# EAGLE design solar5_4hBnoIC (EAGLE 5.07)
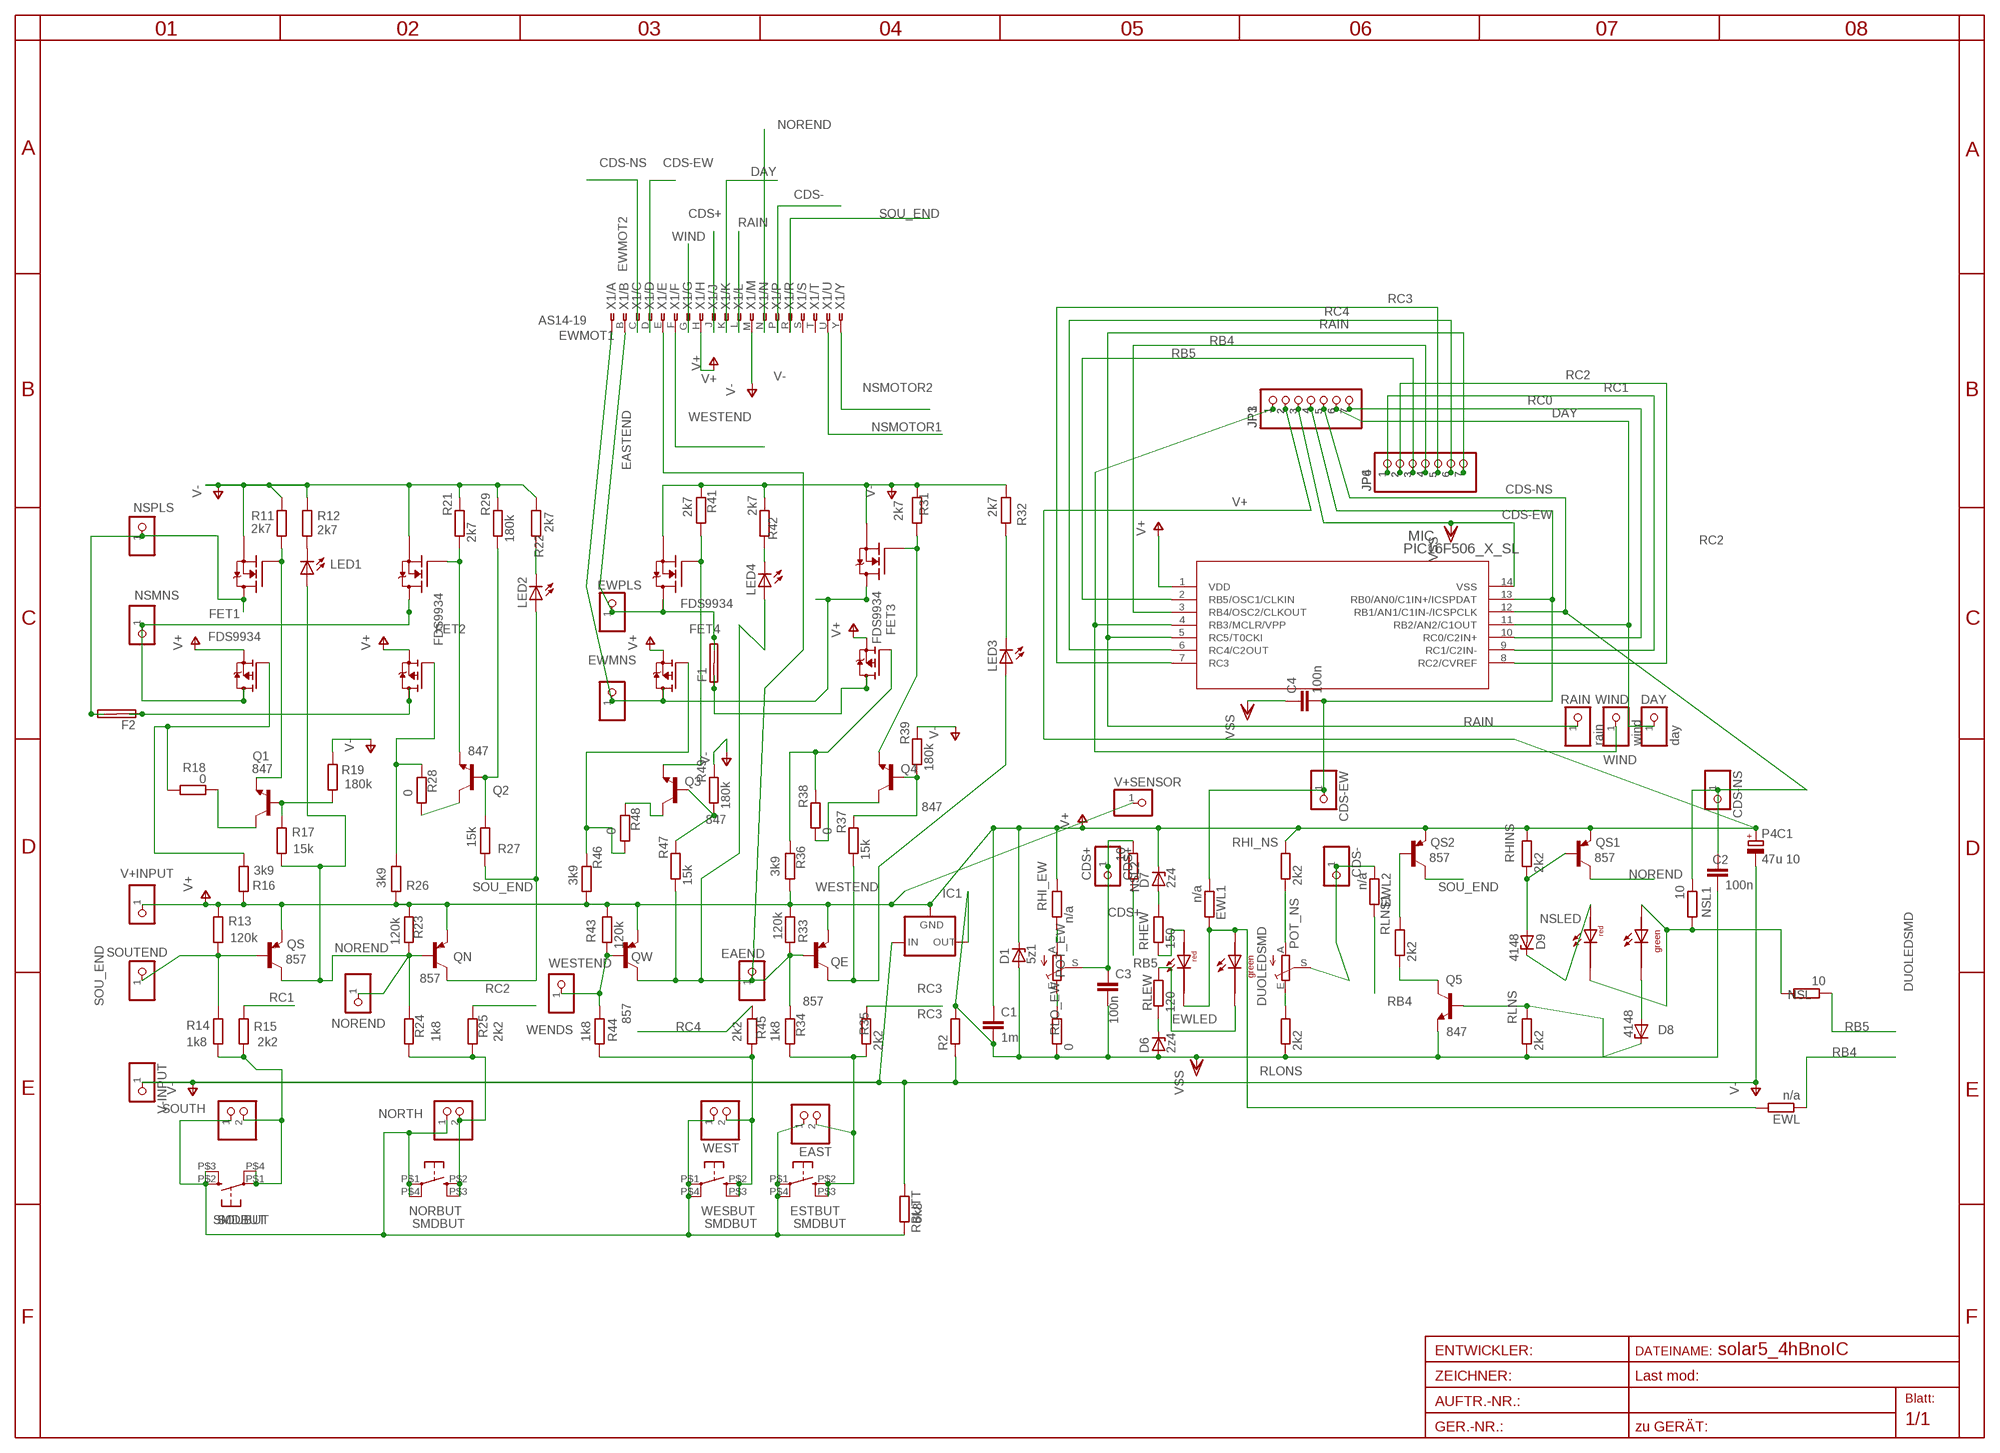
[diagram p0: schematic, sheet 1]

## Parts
C1  1m  C-EUC1206  [C1206]
C2  100n  C-EUC1206  [C1206]
C3  100n  C-EUC1206  [C1206]
C4  100n  C-EUC1206  [C1206]
CDS+  CDS+  PINHD-1X1INCH  [1X01]
CDS-  PINHD-1X1INCH  [1X01]
CDS-EW  PINHD-1X1INCH  [1X01]
CDS-NS  PINHD-1X1INCH  [1X01]
D1  5z1  ZENER-DIODESOD80C  [SOD80C]
D6  2z4  ZENER-DIODESOD80C  [SOD80C]
D7  2z4  ZENER-DIODESOD80C  [SOD80C]
D8  4148  ZENER-DIODESOD80C  [SOD80C]
D9  4148  ZENER-DIODESOD80C  [SOD80C]
DAY  day  PINHD-1X1INCH  [1X01]
EAEND  PINHD-1X1INCH  [1X01]
EAST  PINHD-1X2STR  [1X02]
ESTBUT  SMDBUT  [SMD10/5]
EWL  n/a  R-EU_R0603  [R0603]
EWL1  n/a  R-EU_R0805  [R0805]
EWL2  n/a  R-EU_R0402  [R0402]
EWLED  DUOLEDSMD  [DUOLEDSMD]
EWMNS  PINHD-1X1INCH  [1X01]
EWPLS  PINHD-1X1INCH  [1X01]
F1  SHK20L7MM5  [7MM5]
F2  SHK20L7MM5  [7MM5]
FET1  FDS9934  [SO-8]
FET2  FDS9934  [SO-8]
FET3  FDS9934  [SO-8]
FET4  FDS9934  [SO-8]
IC1  79LXX  [79LXX]
JP1  PINHD-1X7  [1X07]
JP3  PINHD-1X7  [1X07]
JP4  PINHD-1X7  [1X07]
JP6  PINHD-1X7  [1X07]
LED1  LEDCHIPLED_1206  [CHIPLED_1206]
LED2  LEDCHIPLED_1206  [CHIPLED_1206]
LED3  LEDCHIPLED_1206  [CHIPLED_1206]
LED4  LEDCHIPLED_1206  [CHIPLED_1206]
MIC  PIC16F506_X_SL  [SOIC14_N_MC]
NORBUT  SMDBUT  [SMD10/5]
NOREND  PINHD-1X1INCH  [1X01]
NORTH  PINHD-1X2STR  [1X02]
NSL  10  R-EU_R0603  [R0603]
NSL1  10  R-EU_R0805  [R0805]
NSL2  10  R-EU_R0603  [R0603]
NSLED  DUOLEDSMD  [DUOLEDSMD]
NSMNS  PINHD-1X1INCH  [1X01]
NSPLS  PINHD-1X1INCH  [1X01]
P4C1  47u 10  CPOL-EUE5-8.5  [E5-8,5]
POT_EW  TRIM_EU-CA6V  [CA6V]
POT_NS  TRIM_EU-CA6V  [CA6V]
Q1  847  BC847ASMD  [SOT23]
Q2  847  BC847ASMD  [SOT23]
Q3  847  BC847ASMD  [SOT23]
Q4  847  BC847ASMD  [SOT23]
Q5  847  BC847ASMD  [SOT23]
QE  857  BC327SMD  [SOT23-BEC]
QN  857  BC327SMD  [SOT23-BEC]
QS  857  BC327SMD  [SOT23-BEC]
QS1  857  BC327SMD  [SOT23-BEC]
QS2  857  BC327SMD  [SOT23-BEC]
QW  857  BC327SMD  [SOT23-BEC]
R2  R-EU_R0805  [R0805]
R11  2k7  R-EU_R1206  [R1206]
R12  2k7  R-EU_R0805  [R0805]
R13  120k  R-EU_R0805  [R0805]
R14  1k8  R-EU_R1206  [R1206]
R15  2k2  R-EU_R0805  [R0805]
R16  3k9  R-EU_R0805  [R0805]
R17  15k  R-EU_R0805  [R0805]
R18  0  R-EU_R0805  [R0805]
R19  180k  R-EU_R1206  [R1206]
R21  2k7  R-EU_R0805  [R0805]
R22  2k7  R-EU_R0805  [R0805]
R23  120k  R-EU_R0805  [R0805]
R24  1k8  R-EU_R0805  [R0805]
R25  2k2  R-EU_R0805  [R0805]
R26  3k9  R-EU_R1206  [R1206]
R27  15k  R-EU_R0805  [R0805]
R28  0  R-EU_R0805  [R0805]
R29  180k  R-EU_R0805  [R0805]
R31  2k7  R-EU_R0805  [R0805]
R32  2k7  R-EU_R0805  [R0805]
R33  120k  R-EU_R0805  [R0805]
R34  1k8  R-EU_R0805  [R0805]
R35  2k2  R-EU_R0805  [R0805]
R36  3k9  R-EU_R0805  [R0805]
R37  15k  R-EU_R0805  [R0805]
R38  0  R-EU_R0805  [R0805]
R39  180k  R-EU_R1206  [R1206]
R41  2k7  R-EU_R0805  [R0805]
R42  2k7  R-EU_R0805  [R0805]
R43  120k  R-EU_R0805  [R0805]
R44  1k8  R-EU_R0805  [R0805]
R45  2k2  R-EU_R0805  [R0805]
R46  3k9  R-EU_R0805  [R0805]
R47  15k  R-EU_R0805  [R0805]
R48  0  R-EU_R0805  [R0805]
R49  180k  R-EU_R0805  [R0805]
RAIN  rain  PINHD-1X1INCH  [1X01]
RBUTT  6k8  R-EU_R0805  [R0805]
RHEW  150  R-EU_R0805  [R0805]
RHI_EW  n/a  R-EU_R0805  [R0805]
RHI_NS  2k2  R-EU_R1206  [R1206]
RHINS  2k2  R-EU_R0805  [R0805]
RLEW  120  R-EU_R0805  [R0805]
RLNS  2k2  R-EU_R0805  [R0805]
RLNS1  2k2  R-EU_R0805  [R0805]
RLO_EW  0  R-EU_R1206  [R1206]
RLONS  2k2  R-EU_R0805  [R0805]
SOUBUT  SMDBUT  [SMD10/5]
SOUTEND  PINHD-1X1INCH  [1X01]
SOUTH  PINHD-1X2STR  [1X02]
V+INPUT  PINHD-1X1INCH  [1X01]
V+SENSOR  PINHD-1X10MM6  [1X01M]
V-INPUT  PINHD-1X10MM6  [1X01M]
WENDS  PINHD-1X1INCH  [1X01]
WESBUT  SMDBUT  [SMD10/5]
WEST  PINHD-1X2STR  [1X02]
WIND  wind  PINHD-1X1INCH  [1X01]
X1  AS14-19  AS14-19OLIVE  [Y28M-19TK]

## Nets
A1: POT_EW.A RHI_EW.1
A2: POT_NS.A RHI_NS.1
CDS+: C3.1 CDS+.1 NSL2.1 POT_EW.S X1.J
CDS-: CDS-.1 EWL2.1 POT_NS.S X1.P
CDS-EW: C4.2 CDS-EW.1 EWL1.1 JP1.4 JP3.4 MIC.13(RB0/AN0/C1IN+/ICSPDAT) X1.D
CDS-NS: C2.1 CDS-NS.1 JP1.5 JP3.5 MIC.12(RB1/AN1/C1IN-/ICSPCLK) NSL1.1 X1.C
DAY: DAY.1 JP1.6 JP3.6 MIC.11(RB2/AN2/C1OUT) X1.K
DRP2: F2.1A F2.1B FET2.5(Q2D2) FET2.6(Q2D)
DRP3: F1.1A F1.1B FET3.5(Q2D2) FET3.6(Q2D)
E2: POT_NS.E RLONS.2
EASTEND: EAEND.1 LED4.A QE.B QW.C R33.2 R34.2 R47.1 X1.E
EWMOT1: EWMNS.1 FET3.7(Q1D2) FET3.8(Q1D1) FET4.5(Q2D2) FET4.6(Q2D) X1.A
EWMOT2: EWPLS.1 F1.2A F1.2B FET4.7(Q1D2) FET4.8(Q1D1) X1.B
F1NG: FET1.2(Q1G) Q1.2(E) R11.1
F1PG: FET1.4(Q2G) R16.2 R18.1
F2NG: FET2.2(Q1G) Q2.2(E) R21.1
F2PG: FET2.4(Q2G) R26.2 R28.2
N$1: D9.A QS1.B RHINS.1
N$2: D8.A NSLED.CGRN
N$3: D8.C Q5.1(B) RLNS.2
N$4: QS2.B RLNS1.2
N$5: LED1.C R12.1
N$6: Q3.1(B) R47.2 R49.1
N$7: FET4.4(Q2G) R46.2 R48.1
N$8: LED2.C R22.1
N$9: R14.1 R15.1 SOUBUT.P$1(P) SOUBUT.P$4(P1) SOUTH.2
N$10: D9.C NSLED.ARED
N$11: EAST.2 ESTBUT.P$2(S) ESTBUT.P$3(S1) R34.1 R35.1
N$12: Q2.3(C) R28.1
N$13: FET3.2(Q1G) Q4.2(E) R31.1
N$14: D7.A RHEW.2
N$15: LED4.C R42.1
N$16: Q5.3(C) RLNS1.1
N$17: NORBUT.P$2(S) NORBUT.P$3(S1) NORTH.2 R24.1 R25.1
N$19: Q1.1(B) R17.2 R19.1
N$20: Q1.3(C) R18.2
N$21: POT_EW.E RLO_EW.2
N$23: Q2.1(B) R27.2 R29.1
N$25: EWLED.ARED RHEW.1
N$26: FET3.4(Q2G) R36.2 R38.2
N$27: D6.C RLEW.1
N$28: EWLED.CGRN RLEW.2
N$29: EAST.1 ESTBUT.P$1(P) ESTBUT.P$4(P1) NORBUT.P$1(P) NORBUT.P$4(P1) NORTH.1 RBUTT.2 SOUBUT.P$2(S) SOUBUT.P$3(S1) SOUTH.1 WESBUT.P$1(P) WESBUT.P$4(P1) WEST.1
N$30: Q4.1(B) R37.2 R39.1
N$31: Q3.3(C) R48.2
N$32: FET4.2(Q1G) Q3.2(E) R41.1
N$33: Q4.3(C) R38.1
N$39: R44.1 R45.1 WESBUT.P$2(S) WESBUT.P$3(S1) WEST.2
N$56: LED3.C R32.1
NOREND: LED1.A NOREND.1 QN.B QS1.C QS.C R17.1 R23.1 R24.2 X1.N
NSMOTOR1: F2.2A F2.2B FET1.7(Q1D2) FET1.8(Q1D1) NSPLS.1 X1.U
NSMOTOR2: FET1.5(Q2D2) FET1.6(Q2D) FET2.7(Q1D2) FET2.8(Q1D1) NSMNS.1 X1.Y
RAIN: JP4.7 JP6.7 MIC.5(RC5/T0CKI) RAIN.1 X1.L
RB4: EWL2.2 EWL.1 JP4.4 JP6.4 MIC.3(RB4/OSC2/CLKOUT)
RB4B: EWL1.2 EWL.2 EWLED.AGRN EWLED.CRED
RB5: JP4.3 JP6.3 MIC.2(RB5/OSC1/CLKIN) NSL2.2 NSL.1
RB5B: NSL1.2 NSL.2 NSLED.AGRN NSLED.CRED
RC0: JP1.7 JP3.7 MIC.10(RC0/C2IN+)
RC1: JP4.1 JP6.1 MIC.9(RC1/C2IN-) R15.2
RC2: JP4.2 JP6.2 MIC.8(RC2/CVREF) R25.2
RC3: JP4.5 JP6.5 MIC.7(RC3) R35.2
RC4: JP4.6 JP6.6 MIC.6(RC4/C2OUT) R45.2
SOU_END: LED2.A QN.C QS2.C QS.B R13.1 R14.2 R27.1 SOUTEND.1 X1.R
V+: C1.1 D1.C D7.C FET1.3(Q2S) FET2.3(Q2S) FET3.3(Q2S) FET4.3(Q2S) IC1.GND JP1.2 JP3.2 MIC.1(VDD) P4C1.+ QE.E QN.E QS1.E QS2.E QS.E QW.E R13.2 R16.1 R23.2 R26.1 R33.1 R36.1 R43.2 R46.1 RHI_EW.2 RHI_NS.2 RHINS.2 V+INPUT.1 V+SENSOR.1 X1.H
V-: FET1.1(Q1S) FET2.1(Q1S) FET3.1(Q1S) FET4.1(Q1S) IC1.IN P4C1.- R2.1 R11.2 R12.2 R19.2 R21.2 R22.2 R29.2 R31.2 R32.2 R39.2 R41.2 R42.2 R49.2 RBUTT.1 V-INPUT.1 X1.M
VSS: C1.2 C2.2 C3.2 C4.1 D1.A D6.A IC1.OUT JP1.3 JP3.3 MIC.14(VSS) Q5.2(E) R2.2 RLNS.1 RLO_EW.1 RLONS.1
WESTEND: LED3.A QE.C QW.B R37.1 R43.1 R44.2 WENDS.1 X1.F
WIND: JP1.1 JP3.1 MIC.4(RB3/MCLR/VPP) WIND.1 X1.G
Unconnected: X1.S X1.T

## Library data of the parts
C1-C4 = rcl-2:C-EU: CAPACITOR, European symbol
CDS+ CDS- CDS-EW CDS-NS DAY EAEND EWMNS EWPLS NOREND NSMNS NSPLS RAIN SOUTEND V+INPUT V+SENSOR V-INPUT WENDS WIND = pinhead(2):PINHD-1X1: PIN HEADER
D1 D6-D9 = diode-1:ZENER-DIODE: Z-Diode
EAST NORTH SOUTH WEST = pinhead:PINHD-1X2: PIN HEADER
ESTBUT NORBUT SOUBUT WESBUT = switch-omron:SMDBUT
EWL EWL1 EWL2 NSL NSL1 NSL2 R2 R11-R19 R21-R29 R31-R39 R41-R49 RBUTT RHEW RHI_EW RHI_NS RHINS RLEW RLNS RLNS1 RLO_EW RLONS = rcl-2:R-EU_: RESISTOR, European symbol
EWLED NSLED = led:DUOLEDSMD
F1 F2 = fuse:SHK20L: FUSE HOLDER 5 x 20 mm, SH contact, SHH1 Schukat, E1073 Buerklin
FET1-FET4 = transistor-fet:FDS9934
IC1 = v-reg:79LXX: VOLTAGE REGULATOR
JP1 JP3 JP4 JP6 = pinhead:PINHD-1X7: PIN HEADER
LED1-LED4 = led:LED: LED
MIC = pic16f506mc:PIC16F506_X_SL
P4C1 = rcl:CPOL-EU: POLARIZED CAPACITOR, European symbol
POT_EW POT_NS = pot:TRIM_EU-: POTENTIOMETER
Q1-Q5 = transistor-npn:BC847*: NPN Transistor
QE QN QS QS1 QS2 QW = transistor-pnp:BC327*: PNP Transistror
X1 = con-deutsch:AS14-19: DEUTSCH Connector

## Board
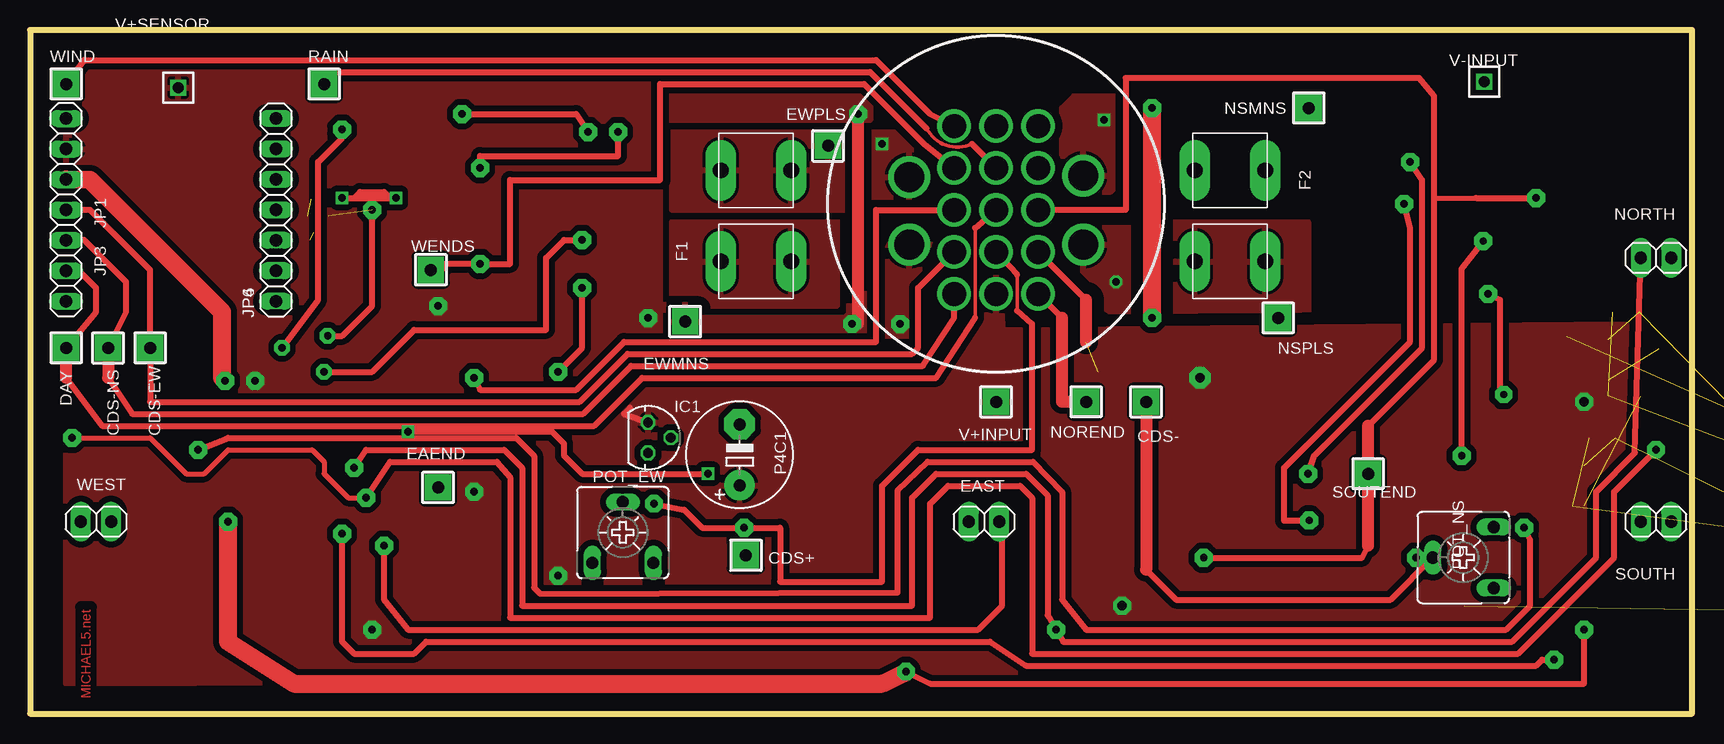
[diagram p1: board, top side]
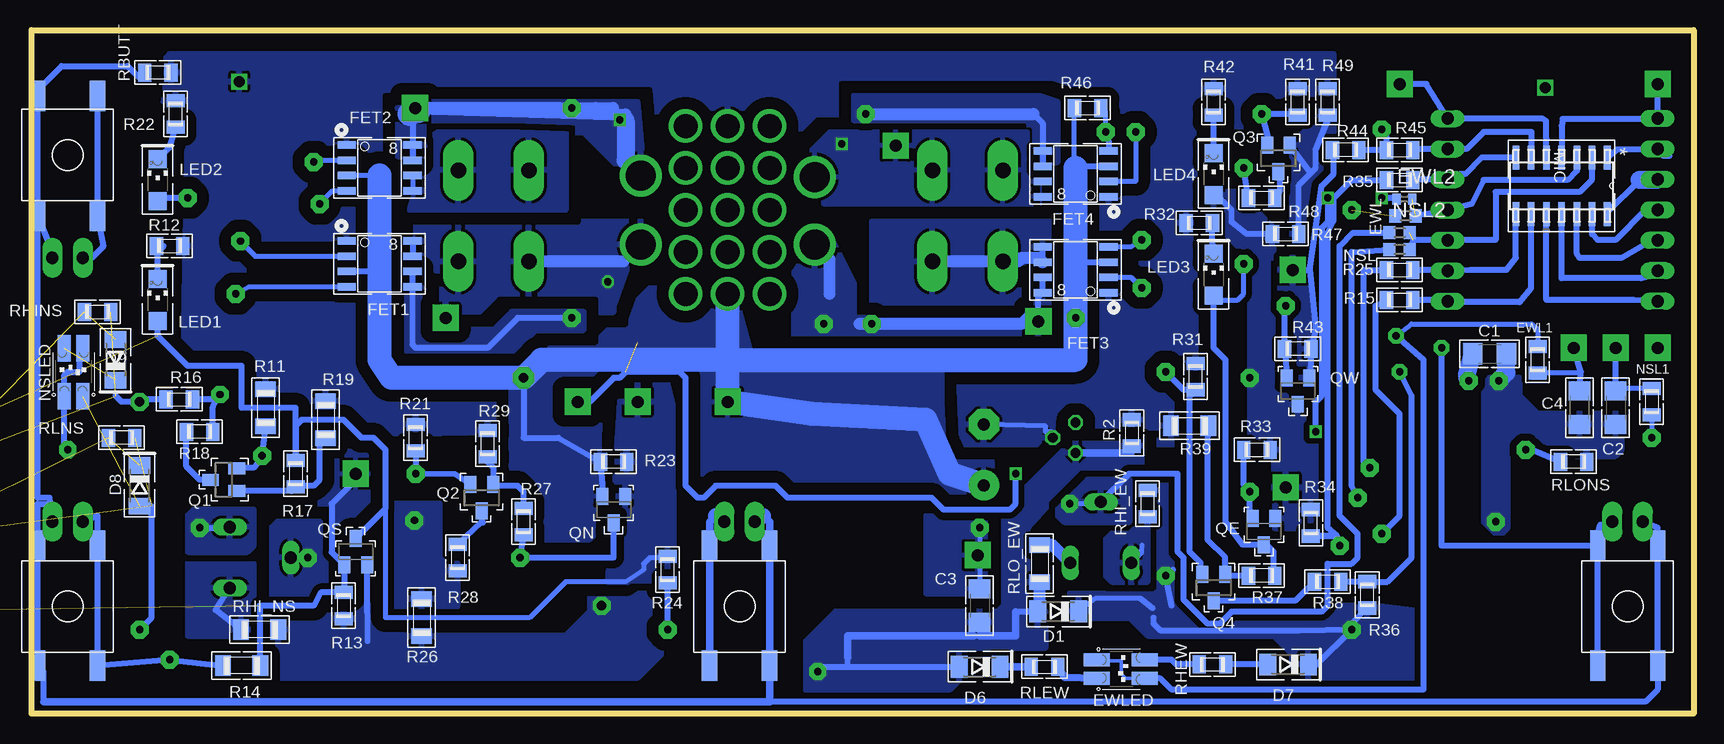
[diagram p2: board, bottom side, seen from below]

Size 138.5 x 57 mm. Coordinates in mm from the lower left corner, seen from the top.
Outline: 138.5,0 138.5,57 0,57 0,0 138.5,0
Copper layers (1*16): Top 0.035mm / dielectric 1.5mm / Bottom 0.035mm
Design rules "default *": minimum track width 40mil, minimum drill 30mil, track to track 8mil, track to pad 8mil, pad to pad 8mil, via to via 8mil, smd to smd 8mil, copper to edge 40mil, drill to drill 8mil, minimum pad ring 8mil, minimum via ring 8mil, stop-mask expansion 4mil, vias tented up to drill 0mil, thermal gap 10mil

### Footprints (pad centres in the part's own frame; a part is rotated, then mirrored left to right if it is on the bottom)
C1206 = smd 1.6 x 1.8: 1 -1.4,0; 2 1.4,0
1X01 = drill 1 pad 2.184 square: 1 0,0
SOD80C = smd 1.4 x 1.8: A 1.7,0; C -1.7,0
1X02 = drill 1.016 pad 1.676 long: 1 -1.27,0; 2 1.27,0
SMD10/5 = smd 1.27 x 2.54: P$1 -2.5,0; P$2 2.5,0; P$3 2.5,10; P$4 -2.5,10
R0603 = smd 1 x 1.1: 1 -0.85,0; 2 0.85,0
R0805 = smd 1.1 x 1.5: 1 -1.1,0; 2 1.1,0
R0402 = smd 0.7 x 0.9: 1 -0.65,0; 2 0.65,0
DUOLEDSMD = smd 1.067 x 2.184: AGRN 0.77,1.95; ARED -0.77,1.95; CGRN 0.77,-2.05; CRED -0.77,-2.05
7MM5 = drill 1.3 pad 2.54 long: 1A -3.8,2.94; 1B -3.8,-2.94; 2A 3.8,2.94; 2B 3.8,-2.94
SO-8 = smd 1.524 x 0.61: 1 -2.743,1.905; 2 -2.743,0.635; 3 -2.743,-0.635; 4 -2.743,-1.905; 5 2.743,-1.905; 6 2.743,-0.635; 7 2.743,0.635; 8 2.743,1.905
79LXX = drill 0.813 octagon: GND -1.27,0; IN 0,1.905; OUT 1.27,0
1X07 = drill 1.016 long: 1 -7.62,0; 2 -5.08,0; 3 -2.54,0; 4 0,0; 5 2.54,0; 6 5.08,0; 7 7.62,0
CHIPLED_1206 = smd 1.5 x 1.5: A 0,-1.75; C 0,1.75
SOIC14_N_MC = smd 1.981 x 0.559: 1 -2.362,3.81; 2 -2.362,2.54; 3 -2.362,1.27; 4 -2.362,0; 5 -2.362,-1.27; 6 -2.362,-2.54; 7 -2.362,-3.81; 8 2.362,-3.81; 9 2.362,-2.54; 10 2.362,-1.27; 11 2.362,0; 12 2.362,1.27; 13 2.362,2.54; 14 2.362,3.81
E5-8,5 = drill 1 pad 2.54 round: + -2.54,0 | drill 1 pad 2.54 octagon: - 2.54,0
CA6V = drill 1.016 long: A -2.54,-2.54; E 2.54,-2.54; S 0,2.54
SOT23 = smd 1 x 1.4: 1 -0.95,-1.1; 2 0.95,-1.1; 3 0,1.1
SOT23-BEC = smd 1 x 1.4: B -0.95,-1.1; C 0,1.1; E 0.95,-1.1
R1206 = smd 1.3 x 1.7: 1 -1.55,0; 2 1.55,0
1X01M = drill 0.914 square: 1 0,0
Y28M-19TK = drill 2.5 pad 3.5 round: A -7.25,-2.875; B -7.25,2.75; U 7.25,-2.875; Y 7.25,2.875 | drill 2 pad 2.54 round: C -3.5,-7; D -3.5,-3.5; E -3.5,0; F -3.5,3.5; G -3.5,7; H 0,-7; J 0,-3.5; K 0,0; L 0,3.5; M 0,7; N 3.5,-7; P 3.5,-3.5; R 3.5,0; S 3.5,3.5; T 3.5,7

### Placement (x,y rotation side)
C1  17,30 0 bottom
C2  6.5,25.5 270 bottom
C3  59.5,9 270 bottom
C4  9.5,25.5 90 bottom
CDS+  59.65,13.2 0 top
CDS-  93,26 90 top
CDS-EW  10,30.5 0 top
CDS-NS  6.5,30.5 90 top
D1  52.95,8.52 180 bottom
D6  59.5,3.9 180 bottom
D7  33.8,4.1 180 bottom
D8  129.5,19 270 bottom
D9  131.5,29.5 90 bottom
DAY  3,30.5 0 top
EAEND  34,18.85 270 top
EAST  79.5,16 0 top
ESTBUT  79.5,14 180 bottom
EWL  24,41.5 180 bottom
EWL1  13,29.5 90 bottom
EWL2  24.1,42.9 0 bottom
EWLED  47.7,3.7 270 bottom
EWMNS  54.6,32.7 90 top
EWPLS  66.5,47.35 90 top
F1  60.5,41.5 90 top
F2  100,41.5 270 top
FET1  109.5,37.5 0 bottom
FET2  109.5,45.5 0 bottom
FET3  51.5,37 180 bottom
FET4  51.5,45 180 bottom
IC1  51.5,23 270 top
JP1  3,42 270 top
JP3  3,42 270 top
JP4  20.5,42 90 top
JP6  20.5,42 90 top
LED1  128,34.5 0 bottom
LED2  128,44.5 0 bottom
LED3  40,36.6 0 bottom
LED4  40,45 0 bottom
MIC  11,44 270 bottom
NORBUT  135.5,41.5 0 bottom
NOREND  88,26 0 top
NORTH  135.5,38 180 top
NSL  24.5,38.7 180 bottom
NSL1  3.5,26 270 bottom
NSL2  24.5,40.1 0 bottom
NSLED  135,28.5 0 bottom
NSMNS  106.55,50.5 0 top
NSPLS  104,33 0 top
P4C1  59.14,21.58 90 top
POT_EW  49.4,15.1 0 top
POT_NS  119.44,13.01 90 top
Q1  122.5,19.5 90 bottom
Q2  101,18 180 bottom
Q3  34.6,46.3 180 bottom
Q4  40,10.5 180 bottom
Q5  not placed on the board
QE  35.81,15.17 180 bottom
QN  90,17 180 bottom
QS  111.5,13.5 0 bottom
QS1  not placed on the board
QS2  not placed on the board
QW  32.98,26.89 180 bottom
R2  46.82,23.39 270 bottom
R11  119,25.5 90 bottom
R12  127,39 0 bottom
R13  112.5,9 270 bottom
R14  121,4 0 bottom
R15  24.5,34.5 0 bottom
R16  126.2,26.2 0 bottom
R17  116.5,20 270 bottom
R18  124.5,23.5 180 bottom
R19  114,24.5 90 bottom
R21  106.5,23 90 bottom
R22  126.5,50 90 bottom
R23  90,21 180 bottom
R24  85.5,12 90 bottom
R25  24.5,37 0 bottom
R26  106,8 90 bottom
R27  97.5,16 90 bottom
R28  103,13 270 bottom
R29  100.5,22.5 90 bottom
R31  41.5,28.1 90 bottom
R32  41.2,40.9 180 bottom
R33  36.39,22 0 bottom
R34  31.9,15.9 90 bottom
R35  24.5,44.5 0 bottom
R36  27.2,9.9 90 bottom
R37  36,11.5 180 bottom
R38  30.5,11 0 bottom
R39  42,24 180 bottom
R41  33,51 90 bottom
R42  40,51 90 bottom
R43  32.99,30.41 180 bottom
R44  29,47 180 bottom
R45  24.5,47 0 bottom
R46  50.5,50.5 0 bottom
R47  34,40 0 bottom
R48  36,43 0 bottom
R49  30.5,51 90 bottom
RAIN  24.5,52.5 0 top
RBUTT  127.98,53.45 180 bottom
RHEW  40.1,4.1 0 bottom
RHI_EW  45.5,17.5 90 bottom
RHI_NS  119.5,7 0 bottom
RHINS  133,33.5 0 bottom
RLEW  54.1,3.9 0 bottom
RLNS  131,23 180 bottom
RLNS1  not placed on the board
RLO_EW  54.5,12.5 90 bottom
RLONS  10,21 180 bottom
SOUBUT  135.5,14 180 bottom
SOUTEND  111.5,20 0 top
SOUTH  135.5,16 180 top
V+INPUT  80.5,26 90 top
V+SENSOR  12.35,52.2 90 top
V-INPUT  121.2,52.7 90 top
WENDS  33.4,37 270 top
WESBUT  5.5,14 180 bottom
WEST  5.5,16 0 top
WIND  3,52.5 0 top
X1  80.5,42 0 top

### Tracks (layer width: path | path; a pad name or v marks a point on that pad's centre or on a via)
A1
  Bottom 0.406: 45.95,14.05 46,13.5 46,13.42 POT_EW.A
  pour Bottom (isolate 0.5): 45.5,16 46.5,15.5 47,15 48.5,15 49,14.5 49,11.5 48.5,11 45.5,11
A2
  Bottom 0.5: RHI_NS.1 123.16,8.64 POT_NS.A
  pour Bottom (isolate 0.5, rank 2): 120,12.5 125.5,12.5 125.5,6.5 120,6.5
CDS+  (via drill 0.6 pad 1.42, 0.6 pad 1.5)
  Top 0.3: 82.25,33.6 82.25,36.6
  Top 0.5: v52,17.5 54.5,17 56,15.5 v59.5,15.5 62.5,15.5 62.5,11 71,11 71,19 74,22 83.5,22 83.5,32.5 82.25,33.6 | 82.25,36.6 X1.J
  Bottom 0.406: v59.5,15.5 59.5,13.55 CDS+.1 59.5,12.55 C3.1 | v52,17.5 50.04,17.5 POT_EW.S
  Bottom 0.5: NSL2.1 28.4,40.1 29.5,39 29.5,16.5 28,15 28,13 28.5,12.5 30.5,12.5 30.5,9 31,8.5 38.5,8.5 39.5,7.5 40.5,7.5 42.5,9.5 42.5,13 43,13.5 43,20 47.04,20 POT_EW.S
  pour Bottom (isolate 0.5): 47,19.5 50.5,19.5 53,17 53,16.5 52.5,16 47,16
  pour Bottom (isolate 0.61): 59,16.5 64,16.5 64,10 59,10
CDS-  (via drill 0.6, 0.6 pad 1.5)  (1 unrouted)
  Top 0.5: 88,34.5 X1.P | 93,12 95.5,9.5 113.39,9.5 POT_NS.S | 30,43 29.5,43.5 27.5,43.5 27,43 v26,43 v30.5,43 | v56.5,20 46,20 44.5,21.5 44.5,22.5 43.5,23.5 v31.5,23.5
  Top 1: 88,30.95 88,34.5 | CDS-.1 93,12
  Bottom 0.5: v115.5,13 POT_NS.S | CDS-.1 92,26 90,28 89.5,28 89,28.5 84.5,28.5 84,28 84,19 83,18 82.5,18 81.5,19 76.5,19 75.5,18 63.5,18 62.5,17 57,17 56.5,17.5 v56.5,20 | EWL2.1 24.9,42.9 25,43 v26,43 | v31.5,23.5 31.5,26 31,26.5 31,40.5 30.5,41 v30.5,43
  pour Bottom (isolate 0.5, rank 2): 114.5,16 118,16 118.5,15.5 118.5,9.5 114.5,9.5 114,11 114,15.5
CDS-EW
  Top 0.5: X1.D 74,35.5 74,30.5 73.5,30 49.8,30 45.8,26 10,26 CDS-EW.1 10,37 5,42 JP3.4
  Bottom 0.406: EWL1.1 9.5,28.4 9.4,28.5
  Bottom 0.5: C4.2 9.4,28.5 CDS-EW.1 | JP3.4 3.04,41.96 4.04,41.96 6.5,39.5 8,39.5 8.46,39.96 MIC.13
CDS-NS
  Top 0.5: CDS-NS.1 8,33.5 8,36 4.5,39.5 JP3.5 | X1.C 77,33 74.4,29 50.1,29 46.1,25 8.5,25 6.5,28
  Top 1: CDS-NS.1 6.5,28
  Bottom 0.406: NSL1.1 6.3,27.1 C2.1
  Bottom 0.5: JP3.5 3.04,39.5 3.5,39.5 3.47,39.47 3.47,39.42 6,38 9.5,38 9.7,38.31 9.73,38.34 MIC.12 | C2.1 6.5,27.8 CDS-NS.1
DAY
  Top 0.3: 78.75,33 78.75,40.5
  Top 0.5: JP3.6 4.12,36.9 5.5,35.5 5.5,33.5 DAY.1 | 78.75,40.5 X1.K | 78.75,33 75.5,28 51,28 47,24 6,24 3,28
  Top 1: 3,28 DAY.1
  Bottom 0.5: MIC.11 11,36.3 4.38,36.3 | 4.38,36.3 2.69,36.8 | JP3.6 4.38,36.3
DRP2
  Bottom 0.406: FET2.6 FET2.5
  pour Bottom (isolate 1): 105,48.5 94,48.5 94,42 107,42
DRP3
  Bottom 0.5: FET3.6 FET3.5
  Bottom 1: F1.1B F1.1A 56.3,37.7 56,38 54.5,38 54.5,37.89 FET3.6
  pour Top (isolate 1): 53.5,41 70,41 70,34 53.5,34
  pour Bottom (isolate 1): 53.5,41 68.5,41 68.5,34 53.5,34
E2  (via drill 0.6 pad 1.5)
  Top 0.5: v14,22 16.5,23 40.5,23 42,21.5 42,10.5 42.5,10 72.3,10.1 72.3,18.6 74.8,21 83.6,21 86,18.5 86,9.5 88,7 123,7 125,9 125,14.5 v124.5,15.5
  Bottom 0.5: v124.5,15.5 122.03,15.5 POT_NS.E | RLONS.2 13.5,22 v14,22
  pour Bottom (isolate 0.5): 120,17 125,17 125.5,16.5 125.5,13.5 120.5,13.5 120,14
EASTEND  (via drill 0.6 pad 1.5)
  Top 0.5: v37,28 37.5,27 45.5,27 49.5,31 70.5,31 70.5,42 X1.E
  Bottom 0.5: EAEND.1 33.57,18.92 | LED4.A 39.75,43.25 38.5,42 38.5,41 37.25,40 R47.1 35.5,39.6
  pour Bottom (isolate 0.5, rank 4): 37,43.5 40.5,43.5 40.5,41.5 37,38 37,23 35,23 35,15.5 31.5,15.5 31.5,24 35,27.5 35,40.5 36,41.5
EWMOT1  (via drill 0.6 pad 1.5)
  Top 1: v69,50 69,32.5 v68.5,32.5
  Bottom 0.5: EWMNS.1 54.6,34.74 FET3.8 FET3.7 | 55,50 54.24,49.24 FET4.5 FET4.6
  Bottom 1: EWMNS.1 55.3,33.2 56,32.5 v68.5,32.5 69.5,32.5 | 72,35 72,37.88 X1.A | v69,50 55,50
  other vias: 72.5,32.5
  pour Bottom (isolate 1, rank 2): 53.5,34.5 58.5,34 69,34 72,40 75,40 75,31.5 53.5,31.5
  pour Top (isolate 0.5, rank 2): 53.5,34.5 58.5,34 69,34 72,40 75,40 75,31.5 53.5,31.5
  pour Bottom (rank 2): 54.5,51.5 70,51.5 70,49.5 55.5,49.5 54.5,46 53,46 53,51
  pour Top (isolate 0.5, rank 2): 70,51.5 70,49.5 53,49.5 53,51.5
EWMOT2  (via drill 0.6)
  other vias: 71,47.5
  pour Bottom (isolate 0.61): 54.5,44.5 55.5,44.5 55.5,48.5 72,48.5 73.5,47 73.5,45 72.5,42.5 54.5,42.5
  pour Top (isolate 0.61): 53.5,42 53.5,48.5 72.5,48.5 74,47 74,45 73,42
F1NG  (via drill 0.6 pad 1.5)
  Top 0.5: v119.3,21.5 119.3,37.1 120.1,38.1 v121.1,39.4
  Bottom 0.406: FET1.2 119.86,38.13 v121.1,39.4
  Bottom 0.5: v119.3,21.5 R11.1 | v119.3,21.5 118.9,21.4 | v119.3,21.5 120,20.5 121.35,20.5 Q1.2
F1PG  (via drill 0.6 pad 1.42, 0.6 pad 1.5)
  Top 0.5: v122.8,26.6 122.5,27 122.5,34.5 v121.5,35
  Bottom 0.406: FET1.4 120.41,35.59 v121.5,35
  Bottom 0.5: R16.2 123.2,26.2 v122.8,26.6 123.4,25.6 R18.1
F2NG  (via drill 0.6 pad 1.5)
  Top 0.5: v115,46 116,44.5 116,30.5 107,21.5 v106.5,20
  Bottom 0.406: FET2.2 115,46.13 v115,46
  Bottom 0.5: Q2.2 103.2,19.95 v106.5,20 106.4,21.9 R21.1
F2PG  (via drill 0.6 pad 1.5)
  Top 0.5: v114.5,42.5 115,40.5 115,31 104.5,20.5 104.5,16.1 v106.6,16.1
  Bottom 0.406: FET2.4 113.41,43.59 v114.5,42.5
  pour Bottom (isolate 0.5, rank 3): 104.5,17.5 108.5,17.5 109,17 109,9 108.5,8.5 103.5,8.5 103,9 103,12.5 104,12.5 104.5,13
N$1  (2 unrouted)
N$2  (1 unrouted)
N$3  (2 unrouted)
N$4  (1 unrouted)
N$5
  Bottom 0.5: R12.1 127.5,39 128,38.5 LED1.C
N$6
  Bottom 0.5: R47.2 32.9,44.05 31.93,45.08 | 31.93,45.08 Q3.1 | R49.1 30.5,49.5 31.5,47 31.5,45.5 31.93,45.08
  pour Bottom (isolate 0.61, rank 3): 30.5,50 31,50 33.5,47.5 33.5,39.5 32,39.5 31.5,40 31.5,44 30,45.5 30,49.5
N$7  (via drill 0.6 pad 1.5)
  Top 0.5: v37.5,45.5 37.5,46.5 49,46.5 v49,48.5
  Bottom 0.406: 48.76,47.74 49,47.99 v49,48.5 49,50.2 R46.2
  Bottom 0.5: R48.1 v37.5,45.5 | 48.76,47.74 FET4.4
N$8
  Bottom 0.5: R22.1 127,47.25 LED2.C
N$9  (via drill 0.6 pad 1.5)
  Top 0.5: v127,4.5 126,4.5 125.5,4 83,4 80,6 33,6 32,5 27,5 26,6 v26,15
  Bottom 0.5: SOUTH.2 133,16.5 SOUBUT.P$1 SOUBUT.P$4 v127,4.5 R14.1 | R15.1 26.5,34 26.5,27 24.5,25 24.5,16.5 v26,15
N$10  (1 unrouted)
N$11  (via drill 0.6 pad 1.5)
  Top 0.5: v29.5,14 29.5,9.5 31.5,7 79,7 81,9 81,15.97 EAST.2
  Bottom 0.5: R35.1 28.5,44.5 30,43 30,41.1 30.5,40.1 30.5,15.5 29.7,14.8 R34.1 29.8,14.8 v29.5,14
  Bottom 0.61: ESTBUT.P$3 ESTBUT.P$2 82,16 81.5,16.5
  Bottom 1.27: EAST.2 81.5,16.5
N$12
  Bottom 0.5: Q2.3 100.9,15.9 101,16 R28.1
N$13  (via drill 0.6 pad 1.5)
  Top 0.5: v46,35.5 46,30.5 v44,28.5
  Bottom 0.406: FET3.2 46.87,36.37 v46,35.5
  Bottom 0.5: Q4.2 41.1,12.6 42,13.5 42,26.5 R31.1 42.5,27 v44,28.5
N$14
  Bottom 0.5: D7.A RHEW.2
N$15
  Bottom 0.5: LED4.C R42.1
N$16  (1 unrouted)
N$17  (via drill 0.6 pad 1.5)
  Top 0.5: NORTH.2 133.73,21.73 130.5,18.5 130.5,13 123.5,6 86.1,6 v85.5,7 84.8,8.2 84.8,18.2 83,20 75.5,20 73.5,18 73.5,9 41,9 41,20.5 39.5,22 28,22 v27,20.5
  Bottom 0.5: NORBUT.P$3 NORBUT.P$2 132.5,39 133.5,38 NORTH.2 | R25.1 27.5,37 27.5,21 v27,20.5 | v85.5,7 R24.1
N$19
  Bottom 0.5: Q1.1 116.85,18.55 R17.2 116.4,19 115,19 114.5,19.5 114.5,22.5 114.05,22.95 R19.1
N$20
  Bottom 0.5: Q1.3 124.5,19.5 125.6,20.6 R18.2
N$21
  Bottom 1: RLO_EW.2 53.43,14.05 POT_EW.E
N$23
  Bottom 0.5: R29.1 100.5,21 100,20.5 100,19.15 Q2.1 99.95,19 98,19 97.5,18.5 R27.2
N$25
  Bottom 0.406: 45.72,4.5 EWLED.ARED
  Bottom 0.5: RHEW.1 43.1,4.1 43.5,4.5 45.72,4.5
N$26  (via drill 0.6 pad 1.27, 0.6 pad 1.5)
  Top 0.5: v24.5,28.5 28.5,28.5 32,32 43,32 43,38 44.5,39.5 v46,39.5
  Bottom 0.406: FET3.4 46.91,38.91 v46,39.5
  Bottom 0.5: v24.5,28.5 23.5,26.5 23.5,13 25.5,11 R36.2 R38.2
N$27
  Bottom 0.61: RLEW.1 D6.C
N$28
  Bottom 0.61: EWLED.CGRN 52.41,3.03 RLEW.2
N$29
  Bottom 0.5: WEST.1 3,15.5 WESBUT.P$1 WESBUT.P$4 3,2 4,1 77,1 | 137.5,1 137.5,3.5 SOUBUT.P$3 SOUBUT.P$2 138,17.5 137,17.5 SOUTH.1 137,18 138,18 NORBUT.P$1 | NORTH.1 137,39 NORBUT.P$1 | NORBUT.P$1 NORBUT.P$4 137.5,52.5 136,54 130.5,54 129.58,53.08 RBUTT.2
  Bottom 0.61: 137.5,1 77,1 ESTBUT.P$4 ESTBUT.P$1 77,16 77.5,16.5
  Bottom 1.27: 77.5,16.5 EAST.1
N$30
  Bottom 0.5: R39.1 40.5,22.1 40.5,15.5 40.5,14.5 39.05,13.05 Q4.1 38.95,11.5 R37.2
N$31
  Bottom 0.406: 34.5,44.5 34.5,45.1 Q3.3
  Bottom 0.5: 34.5,44.5 34.5,43.5 R48.2
N$32  (via drill 0.6 pad 1.5)
  Top 0.5: v46.5,48.5 45.5,50 v36,50
  Bottom 0.406: FET4.2 46.5,44.37 v46.5,48.5
  Bottom 0.5: Q3.2 35.5,48.05 v36,50 33.6,50 R41.1
N$33
  Bottom 0.5: Q4.3 33.2,9.4 R38.1
N$39  (via drill 0.6 pad 1.27, 0.6 pad 1.5)
  Top 0.5: v26,48.7 26,48 24,46 24,34.5 v21,30.5
  Bottom 0.5: R44.1 R45.1 25.6,48.1 v26,48.7 | v21,30.5 21,14 WESBUT.P$2 | WEST.2 7.77,15.73 8,15 WESBUT.P$2 | WESBUT.P$3 WESBUT.P$2
N$56
  Bottom 0.5: LED3.C 40.1,39.5 R32.1
NOREND  (1 unrouted)
  Top 0.5: 86,33 X1.N
  Top 1: 86,33 86,26 NOREND.1
  Bottom 0.406: 109,17.1 109,8 97,8 94,11 89,11 87.5,12 87.5,12.5 87,13 85.6,13 R24.2
  Bottom 0.5: LED1.A 128,31.5 125.5,29 121,29 121,25.5 116.5,25.5 R17.1 116.5,24 116,24.5 112.5,24.5 111,23 110,23 109,22 109,17.1 QS.C
  pour Bottom (isolate 0.61, rank 3): 85.5,27.5 88,27.5 89.5,26 90.5,11 85.5,11 85,11.5 85,25.5
NSMOTOR1  (via drill 0.6)
  Bottom 0.406: X1.U 87.75,39.41
  Bottom 0.5: FET1.8 FET1.7
  Bottom 1: 89.17,37.7 F2.2B
  other vias: 90.5,36
  pour Bottom (isolate 1, rank 4): 87.5,41 106.5,41 106.5,33.5 90,33.5 90,34
  pour Top (isolate 1, rank 4): 87.5,41 106.5,41 106.5,33.5 90,33.5 87.5,35
NSMOTOR2  (via drill 0.6, 0.6 pad 1.5)
  Top 1.5: v93.5,33 v93.5,50.5
  Bottom 0.5: v93.5,33 98,33 100.5,30.5 106.5,30.5 106.76,30.76 FET1.5 FET1.6 | 91.5,50.5 NSMNS.1 106.76,50.29 FET2.8 FET2.7 | v93.5,50.5 94.5,50.5
  Bottom 1: 106.26,50.24 106,50.5 94.5,50.5 91.5,50.5 90.05,50.5 | 89,49.46 89,49.95 NSMNS.1
  Bottom 1.5: X1.Y 89,46.13 89,49.46
  Bottom 2: 106.26,50.24 106.76,50.24 107,50
  other vias: 89.5,49.5
  pour Bottom (isolate 1, rank 2): 92.5,33.5 98.5,33.5 100,32 105.5,32 105.5,35 106,35.5 107.5,35.5 108,35 108,29.5 107.5,29 99.5,29 96.5,32 92.5,32
  pour Bottom (isolate 0.5, rank 2): 88,51 107,51 108,50.5 108,46.5 106,46.5 104,48.5 92.5,48.5 89.5,45.5 87.5,45.5
  pour Top (isolate 0.61, rank 3): 86,45.5 86,50.5 87,51.5 91,51.5 91,44.5 90,43.5 87.5,43.5
RAIN
  Top 0.3: 74.7,48.8 arc87 78.5,47.5
  Top 0.5: RAIN.1 25.5,53.5 70,53.5 74.7,48.8 | 78.5,47.5 X1.L
  Bottom 0.5: RAIN.1 22.28,52.5 JP6.7 12.62,49.62 12.3,49.4 12.3,47.99 12.27,47.96 MIC.5
RB4  (1 unrouted)
  Bottom 0.5: MIC.3 9.73,45.27 10.5,44.5 17.5,44.5 18.5,42.5 JP6.4 EWL.1
RB4B  (via drill 0.6 pad 1.27, 0.6 pad 1.5)  (1 unrouted)
  Top 0.5: v24.8,31.5 26,31.5 28.5,34 v28.5,42
  Bottom 0.3: EWLED.AGRN 47.33,2.93 47.7,3.3 47.7,4.4 49.38,4.4
  Bottom 0.406: EWL1.2 13,32 13.5,32.5 23.5,32.5 v24.8,31.5
  Bottom 0.5: EWLED.AGRN 44.43,2.93 43.5,2 22.5,2 22.5,29.5 v24.8,31.5
  Bottom 0.61: 49.38,4.4 EWLED.CRED
RB5  (1 unrouted)
  Bottom 0.5: NSL.1 23.36,39.46 JP6.3 16.5,39.5 16.5,43.5 9.5,43.5 8.46,44.54 MIC.2
RB5B  (via drill 0.6 pad 1.42, 0.6 pad 1.5)
  Top 0.406: v28,18 26.5,18 24.5,20 24.5,21 23.5,22 16.5,22 14.5,20 13,20 10,23 v3.5,23
  Top 0.5: v28,18 30,21 38.9,21 40,19.7 40,8 75,8 75,17.5 76.5,19 82.5,19 83.5,18 83.5,5 124,5 132,13 132,18.5 v135.5,22
  Bottom 0.406: NSL1.2 v3.5,23
  Bottom 0.5: NSLED.AGRN 134.5,30.18 134.5,28.5 135.5,28.5 135.77,28.23 NSLED.CRED 135.77,22.23 v135.5,22 | NSL.2 28.5,38.5 28.5,19 v28,18
RC0
  Bottom 0.5: MIC.10 12.27,34.5 5,34.5 2.23,34.3 2.92,34.3 JP3.7
RC1
  Bottom 0.5: MIC.9 13.54,35.46 14.5,34.3 20.38,34.3 JP6.1 21,34.38 | 21,34.38 21.33,34.38 | R15.2 21.12,34.5 21,34.38
RC2
  Bottom 0.5: MIC.8 14.81,37.99 15.6,37 18.58,37 JP6.2 20.58,37 R25.2
RC3
  Bottom 0.5: MIC.7 17.64,46.36 19,45 19.46,45 JP6.5 23.36,44.54 R35.2
RC4
  Bottom 0.5: MIC.6 13.5,46.4 13.5,48.5 17.5,48.5 18.92,47.08 JP6.6 23.32,47.08 R45.2
SOU_END  (via drill 0.6 pad 1.5)  (1 unrouted)
  Top 0.406: 117,43 120.5,43
  Top 0.5: 111.5,24 117,29.5 117,43 117,51.5 115.75,53 91.3,53 91.3,42 X1.R | 120.5,43 v125.5,43 | 111.5,14 111,13 v97.8,13
  Top 1: 111.5,24 SOUTEND.1 111.5,14
  Bottom 0.5: R14.2 119.5,4.05 119.5,9 115,9 114.4,10.1 R13.1 112.45,10.65 QS.B 113.5,13.45 113.5,17.5 111.5,19.5 SOUTEND.1 | v125.5,43 127.75,43 LED2.A | QN.C 90,13 v97.8,13 R27.1
  pour Bottom (isolate 1, rank 3): 109.5,22.5 113.5,22.5 114.5,21.5 114.5,14.5 114,14 112.5,14 111.5,15 109,17.5 109,20.5
V+  (via drill 0.6 pad 1.5, 0.8 pad 1.5, 0.8 pad 1.78)  (3 unrouted)
  Top 0.5: IC1.GND 49.5,25 50,25.5 | v34,34 34.5,34
  Bottom 0.406: 46.1,9.6 49.87,9.6 D1.C | 59,19 59,19.18 P4C1.+ | 80.5,29.5 81,29.5 | 109.86,44.87 FET2.3 | R46.1 51.6,46.2 51.5,45.5
  Bottom 0.5: MIC.1 6.37,47.04 3.04,47.04 2.5,46.5 2,46.5 2.58,47.08 JP3.2 | 46.1,9.6 45.1,8.8 | 131.5,26.5 131,26 130,26 | D7.C 31.4,4.1 v28.5,7 | 130,26 v129.5,26 | QS.E 110.55,10.65 110.5,6.06 | v97.5,28 97.5,23 94.6,23 R23.2 90.95,19.15 QN.E | R16.1 129.8,26.2 130,26 | v28.5,7 32.9,6.9 44.4,6.9 45,7.5 45,8 | QW.E 33.92,28.25 R43.2 34.09,33.91 v34,34 | v28.5,7 28.5,7.5 R36.1 | 43.5,9 v44,11.5 43.4,12 | QE.E 37,17.02 v37,18.5 37.49,19.01 R33.1 | FET1.3 109.5,36.87 109.5,37 | 109.5,44.87 109.86,44.87 | FET3.3 51.37,37.63 51.5,37.5 | FET4.3 51.23,45.63 51.6,46.2
  Bottom 1.016: V+INPUT.1 80.5,29.5
  Bottom 1.5: 109.5,44.87 109.5,45 | C1.1 18.9,28.2 v18.75,27.75
  Bottom 2: 59,19 62,20 64,24.5 73.5,25 V+INPUT.1 X1.H | 80.5,29.5 51.5,29.5 v51.5,33 51.5,37.5 51.5,45.5 | 109.5,44.87 109.5,37 109.5,29.5 108.5,28 v97.5,28 96,29.5 81,29.5
  other vias: 91,9
  pour Top (isolate 0.5, rank 3): 3,55 80,55 80.5,50 81,32 133,32.5 133,3 3,2.5
  pour Bottom (isolate 1): 86,10 92,10 92,8.5 94,6.5 107.5,6.5 108.5,7.5 108.5,8 109.5,9 113.5,9 115,7.5 118.5,7.5 119,7 119,4 118,3 88,3 86,5
  pour Bottom (isolate 0.5, rank 3): 42.5,19.5 45,19.5 45,12 47,10 52,10 52,8 47,8 45.5,6.5 35,6.5 33.5,5 33.5,4 32.5,3 22.5,3 22.5,8.5 26.5,9 42,9 42.5,9.5
  pour Bottom (isolate 1, rank 5): 80,35.5 87,35.5 92,30.5 96.5,30.5 99,28 99,16.5 97,14.5 92,14.5 91,15.5 91,25.5 89.5,27 85,27 83.5,25.5 83.5,13.5 83,13 62,13 58,17 58.5,21.5 62.5,21.5 62.5,30 78.5,30
V-
  Bottom 0.406: IC1.IN 53.5,23.5 54,23.5 54,23.97 P4C1.-
  pour Bottom (isolate 1, rank 4): 30,55 127,55 127.5,54.5 127.5,51 125.5,51 126,23 100,23.5 100,29 97,33 87.5,33 84.5,36 77.5,36 77,35.5 61.5,33.5 61,22.5 41,22.5 41,49 30,49
VSS  (via drill 0.6 pad 1.42, 0.6 pad 1.5)  (2 unrouted)
  Top 0.5: v73,3.5 75,2.5 129.5,2.5 v129.5,7
  Top 1.5: v73,3.5 71,2.5 22,2.5 16.5,6 v16.5,16 | JP3.3 5,44.5 16,33.5 16,28 v16.25,27.75
  Bottom 0.406: 60,6.5 59.5,6.5 C3.2
  Bottom 0.5: v129.5,7 128.5,8 128.5,17.3 | v16.5,16 16.5,16.5 | MIC.14 7.19,41.81 4.5,44.5 | JP3.3 3.04,44.5 | D1.A 56.48,8.52 56.5,8.5 | 70.5,3.9 D6.A | 70.5,3.9 72.6,3.9 v73,3.5 | 70.5,3.9 70.5,4.7
  Bottom 0.61: 59.5,6.5 56.5,6.5 56.5,8.5 | 60,6.5 70.5,6.5 70.5,4.7 | IC1.OUT 46.89,21.73 R2.2
  Bottom 1: RLO_EW.1 54.5,8.67 D1.A
  Bottom 1.5: 3.04,44.5 4.5,44.5 | v16.25,27.75 15.6,28.4 C1.2
  pour Bottom (isolate 0.5, rank 2): 46,22.5 52,22.5 57.5,17 57.5,9 58,8.5 71.5,8.5 74,6 74,2 62,2 61,3 61,5 60.5,5.5 54,5.5 54,8.5 55.5,10 55.5,15.5 51,20.5 46,20.5
  pour Bottom (isolate 0.61): 6,25 13,25 14.5,26.5 14.5,28 17,28 17.5,27.5 17.5,16 16.5,15 16,15 15.5,15.5 15.5,21.5 6.5,21.5 6,22 6,24
WESTEND  (via drill 0.6 pad 1.5)
  Top 0.5: X1.F 74.5,47.5 69.5,52.5 52.5,52.5 52.5,44.5 40,44.5 40,37.5 v37.5,37.5 34.5,37.5 34.4,37.1 WENDS.1
  Bottom 0.406: 40,34.5 38,34.5 37.5,35 v37.5,37.5
  Bottom 0.5: QW.B 31.89,29.12 R43.1 31.5,32.02 32,37 | R44.2 30,46.9 30,45 31,44 32,37 | WENDS.1 32,37 | 39.95,34.5 LED3.A 40,34.5 40,30.5 39,29.5 39,16 37.57,14.07 QE.C 35.57,14.07 35,13.5 35,11.6 R37.1
  pour Bottom (isolate 0.5, rank 3): 30,38 34,38 34.5,37.5 34.5,29 33.5,28 30,28
WIND
  Top 0.5: WIND.1 4.5,54.5 70.5,54.5 75,50 X1.G
  Bottom 0.5: MIC.4 11,49 10.92,49.58 2.5,49.58 | 2.5,49.58 2.07,49.58 | JP3.1 3,49.5 | JP3.1 WIND.1 | JP3.1 2.54,49.62 2.5,49.58

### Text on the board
Top: MICHAEL5.net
